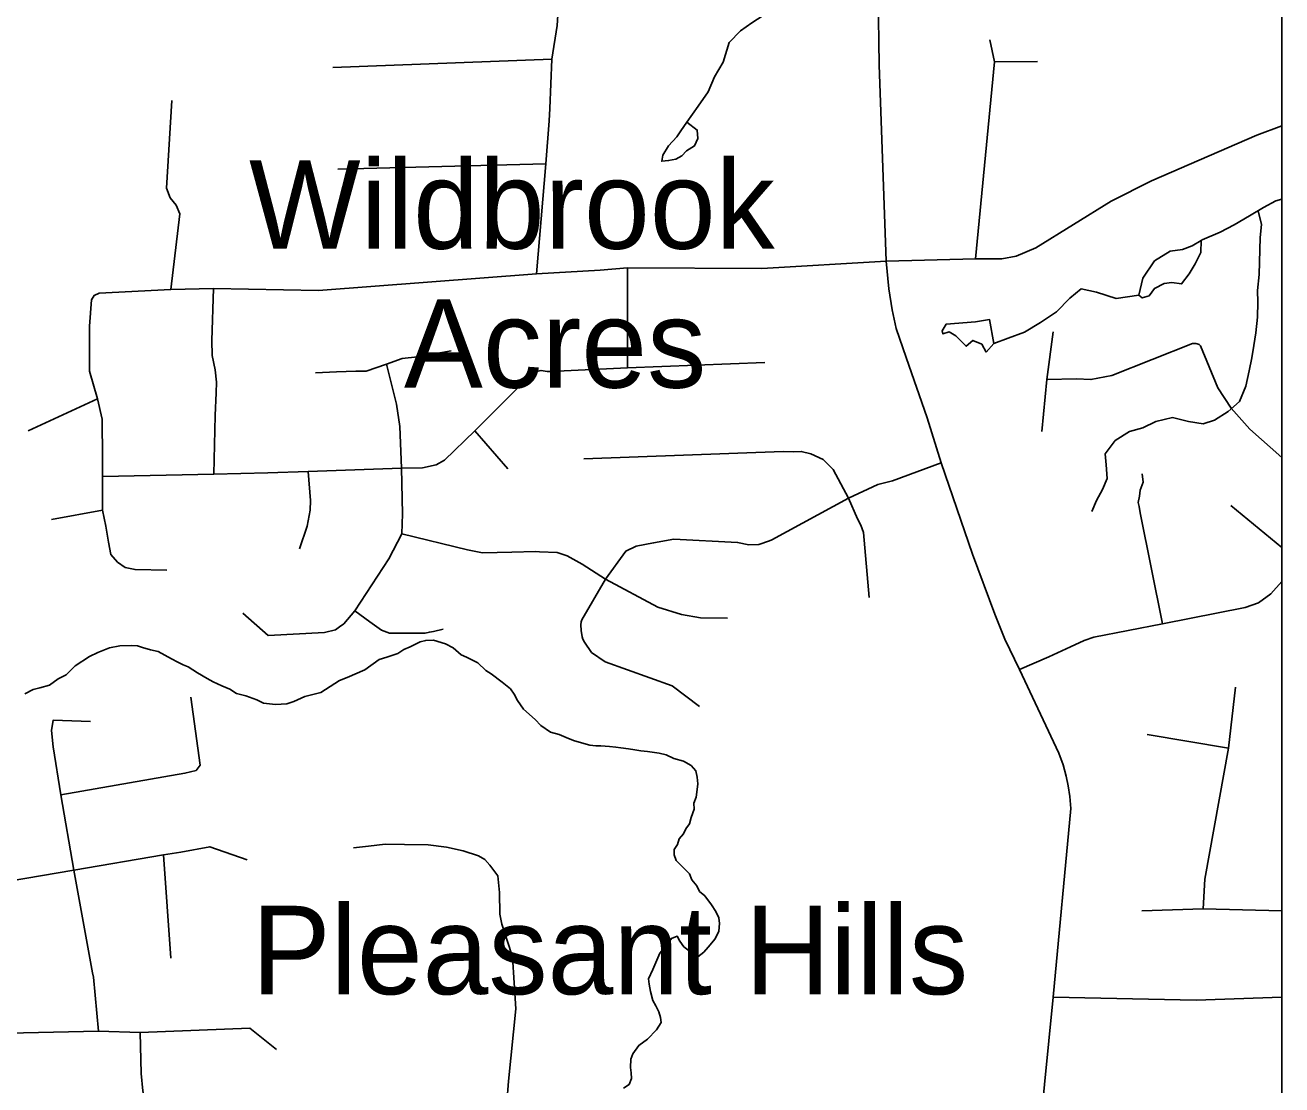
# Model space of a CAD drawing. Extents: x 0 to 34, y 0 to 22.
# Drawn here: x 7.678 to 8.8, y 16.382 to 17.329 of the extents above; entities that cross this region are included whole.
import ezdxf

# ---------------------------------------------------------------- set-up
doc = ezdxf.new("R2010")
doc.units = 0
for name, color, linetype in [('GM_X_County_Road', 7, 'Continuous'), ('GM_X_Minor_Lake', 7, 'Continuous'), ('GM_X_Minor_River', 7, 'Continuous'), ('GM_X_Township_Subdivision', 7, 'Continuous'), ('GM_X_Unincorporated_Text', 7, 'Continuous'), ('SH_Data', 7, 'Continuous')]:
    doc.layers.add(name, color=color, linetype=linetype)

msp = doc.modelspace()

# ---------------------------------------------------------------- linework, layer by layer
at = {"layer": 'GM_X_County_Road'}
for points in [[(8.5763, 16.2655), (8.5957, 16.4605), (8.6116, 16.6291), (8.6107, 16.6398), (8.609, 16.6494), (8.6074, 16.6579), (8.6047, 16.6681), (8.6008, 16.6786), (8.5656, 16.7531), (8.5526, 16.7802), (8.5437, 16.8026), (8.5238, 16.8562), (8.4957, 16.9379), (8.4832, 16.978), (8.4645, 17.0319), (8.4556, 17.0577), (8.4518, 17.0743), (8.4489, 17.0933), (8.4467, 17.1179), (8.4403, 17.2932), (8.4393, 17.3556)], [(8.4467, 17.1179), (8.5265, 17.1201), (8.5499, 17.1201), (8.5627, 17.1224), (8.5803, 17.1297), (8.6475, 17.1715), (8.6835, 17.1897), (8.7776, 17.2303), (8.8, 17.2387)], [(8.5957, 16.4605), (8.7235, 16.4578), (8.8, 16.4607)]]:
    msp.add_lwpolyline(points, dxfattribs=at)
at = {"layer": 'GM_X_Minor_Lake'}
for points in [[(8.2686, 17.2421), (8.2779, 17.2349), (8.2785, 17.2276), (8.2754, 17.2209), (8.2684, 17.2165), (8.2641, 17.212), (8.2588, 17.2091), (8.2523, 17.2077), (8.2462, 17.2071), (8.2471, 17.2127), (8.2522, 17.221), (8.2596, 17.2288), (8.2631, 17.2344)], [(8.2631, 17.2344), (8.2686, 17.2421)], [(8.728, 17.1364), (8.7275, 17.1257), (8.7227, 17.1156), (8.7172, 17.1066), (8.7105, 17.0976), (8.7018, 17.0989), (8.6949, 17.098), (8.6861, 17.0936), (8.6814, 17.0869), (8.6753, 17.0851), (8.6723, 17.0874), (8.6757, 17.1026), (8.6863, 17.1183), (8.7001, 17.1267), (8.7112, 17.1284), (8.72, 17.1316)], [(8.72, 17.1316), (8.728, 17.1364)], [(8.5426, 17.0444), (8.5389, 17.0657), (8.5263, 17.0637), (8.5001, 17.0616), (8.4965, 17.0556), (8.4972, 17.053), (8.5029, 17.0547), (8.5089, 17.0512), (8.5179, 17.0419), (8.524, 17.0471), (8.532, 17.0438), (8.536, 17.0365)], [(8.536, 17.0365), (8.5426, 17.0444)]]:
    msp.add_lwpolyline(points, dxfattribs=at)
at = {"layer": 'GM_X_Minor_River'}
for points in [[(8.4293, 17.4155), (8.4269, 17.4052), (8.4224, 17.3954), (8.4116, 17.3858), (8.4016, 17.3815), (8.3878, 17.3765), (8.3766, 17.3688), (8.3622, 17.3577), (8.351, 17.3474), (8.3367, 17.3374), (8.3266, 17.3308), (8.3166, 17.3235), (8.3064, 17.3131), (8.3011, 17.2957), (8.2932, 17.2826), (8.2875, 17.269), (8.2788, 17.2563), (8.2686, 17.2421)], [(8.7787, 17.1628), (8.7817, 17.1505), (8.7806, 17.1391), (8.7798, 17.106), (8.7783, 17.0916), (8.7785, 17.0813), (8.7781, 17.068), (8.7767, 17.054), (8.7749, 17.0426), (8.7731, 17.0317), (8.7709, 17.0199), (8.7679, 17.0063), (8.7622, 16.9927), (8.7521, 16.9835), (8.7398, 16.9758), (8.7298, 16.9726), (8.7166, 16.9748), (8.7022, 16.9782), (8.6873, 16.9748), (8.6758, 16.969), (8.6639, 16.9659), (8.6512, 16.9578), (8.6422, 16.9459), (8.6431, 16.9359), (8.6439, 16.9237), (8.6399, 16.914), (8.6343, 16.9042), (8.6303, 16.8944)], [(8.8, 17.1733), (8.7947, 17.1718), (8.7836, 17.1657), (8.7712, 17.1583), (8.7573, 17.1503), (8.745, 17.1438), (8.7289, 17.1369), (8.728, 17.1364)], [(8.6723, 17.0874), (8.6521, 17.0845), (8.6344, 17.0902), (8.6208, 17.0931), (8.6107, 17.085), (8.5987, 17.0727), (8.5844, 17.0632), (8.5702, 17.0544), (8.5556, 17.049), (8.5426, 17.0444)], [(7.6774, 16.7314), (7.6847, 16.7354), (7.6908, 16.7367), (7.6992, 16.7391), (7.707, 16.745), (7.7143, 16.7486), (7.7221, 16.7564), (7.7349, 16.7648), (7.7426, 16.7684), (7.7484, 16.7709), (7.753, 16.7727), (7.7622, 16.7743), (7.7728, 16.7748), (7.7778, 16.7743), (7.7823, 16.773), (7.7895, 16.7709), (7.7963, 16.7692), (7.8083, 16.7628), (7.8139, 16.7599), (7.8188, 16.7575), (7.8233, 16.7555), (7.8315, 16.7503), (7.8401, 16.7451), (7.8454, 16.7423), (7.8532, 16.7386), (7.8604, 16.7358), (7.8664, 16.7318), (7.8747, 16.7297), (7.8845, 16.726), (7.8905, 16.7231), (7.9011, 16.7221), (7.9114, 16.7226), (7.9175, 16.7247), (7.9275, 16.729), (7.9417, 16.7327), (7.9583, 16.7433), (7.9653, 16.7462), (7.981, 16.753), (7.9938, 16.7621), (8.0007, 16.7642), (8.0103, 16.7674), (8.0157, 16.771), (8.0215, 16.7735), (8.0304, 16.7779), (8.0354, 16.7792), (8.0422, 16.7794), (8.0531, 16.7761), (8.0599, 16.7725), (8.0669, 16.7662), (8.0718, 16.7641), (8.082, 16.7593), (8.089, 16.7522), (8.0939, 16.7494), (8.1036, 16.7419), (8.111, 16.736), (8.1143, 16.7313), (8.1172, 16.7256), (8.1227, 16.7178), (8.1331, 16.7087), (8.1383, 16.7033), (8.1468, 16.6973), (8.1544, 16.6952), (8.163, 16.6915), (8.1683, 16.6895), (8.1819, 16.6857), (8.1872, 16.6851), (8.1918, 16.685), (8.1994, 16.6844), (8.205, 16.6839), (8.2096, 16.6834), (8.2164, 16.6824), (8.2221, 16.6815), (8.2274, 16.6806), (8.2335, 16.68), (8.2437, 16.6786), (8.2501, 16.6769), (8.2569, 16.6737), (8.2656, 16.6715), (8.2723, 16.6675), (8.2767, 16.6628), (8.2777, 16.6571), (8.2783, 16.651), (8.2778, 16.646), (8.2768, 16.6392), (8.2748, 16.6339), (8.275, 16.6286), (8.2725, 16.6211), (8.2709, 16.6154), (8.2677, 16.6109), (8.2657, 16.6064), (8.2618, 16.6019), (8.2601, 16.597)], [(8.2601, 16.597), (8.2573, 16.5925), (8.2572, 16.5876), (8.259, 16.5826), (8.2664, 16.5752), (8.2708, 16.5708), (8.2729, 16.5654), (8.2774, 16.56), (8.2799, 16.555), (8.2847, 16.551), (8.2906, 16.5429), (8.2946, 16.537), (8.2971, 16.5313), (8.2977, 16.5263), (8.2972, 16.5195), (8.2939, 16.5127), (8.2877, 16.5052), (8.2837, 16.5008), (8.2783, 16.4967), (8.2731, 16.5003), (8.266, 16.5055), (8.2623, 16.5105), (8.2598, 16.5152), (8.2548, 16.513), (8.25, 16.5063), (8.2445, 16.5), (8.2381, 16.4853), (8.2344, 16.477), (8.235, 16.4721), (8.236, 16.4656), (8.2381, 16.4575), (8.241, 16.4529), (8.2435, 16.4475), (8.2449, 16.4425), (8.2455, 16.4379), (8.2415, 16.4315), (8.2333, 16.423), (8.2256, 16.4175), (8.2204, 16.41), (8.2184, 16.4051), (8.2182, 16.3979), (8.2188, 16.3929), (8.2191, 16.388), (8.217, 16.3827), (8.212, 16.3794)]]:
    msp.add_lwpolyline(points, dxfattribs=at)
at = {"layer": 'GM_X_Township_Subdivision'}
for points in [[(8.1461, 17.2541), (8.148, 17.2982), (8.1528, 17.3285), (8.1537, 17.3424)], [(8.5265, 17.1201), (8.5434, 17.2959), (8.5393, 17.3155)], [(7.9524, 17.2908), (8.148, 17.2982)], [(8.5434, 17.2959), (8.5816, 17.2961)], [(7.8077, 17.0927), (7.8158, 17.1603), (7.8125, 17.1679), (7.8072, 17.1745), (7.8039, 17.1832), (7.8085, 17.2614)], [(8.1343, 17.1065), (8.1425, 17.2049), (8.1457, 17.2433), (8.1461, 17.2541)], [(7.9567, 17.2002), (8.1425, 17.2049)], [(8.4467, 17.1179), (8.3354, 17.1114), (8.2156, 17.1119), (8.1912, 17.1098), (8.1343, 17.1065), (7.9395, 17.0917), (7.8457, 17.0934), (7.8077, 17.0927), (7.7436, 17.0894), (7.7391, 17.0873), (7.7369, 17.0833)], [(8.2156, 17.0225), (8.2156, 17.1119)], [(7.8457, 17.0934), (7.8442, 17.047), (7.8446, 17.0337), (7.8473, 17.0209), (7.8485, 17.0097), (7.8481, 17.0003), (7.8473, 16.9802), (7.8462, 16.9276)], [(7.7369, 17.0833), (7.7351, 17.0599), (7.7351, 17.0198), (7.7423, 16.9949), (7.7465, 16.9769), (7.7468, 16.9419), (7.7467, 16.9257), (7.7468, 16.8955), (7.7495, 16.8812), (7.7521, 16.8669), (7.7542, 16.856), (7.7602, 16.8491), (7.767, 16.8444), (7.7757, 16.8424), (7.8041, 16.8418)], [(8.5857, 16.9657), (8.5901, 17.0123), (8.5958, 17.0549)], [(8.5901, 17.0123), (8.6166, 17.0127), (8.6295, 17.0122), (8.6481, 17.0158), (8.7201, 17.0443), (8.7222, 17.0445), (8.7233, 17.0444), (8.7243, 17.0442), (8.7261, 17.0435), (8.7268, 17.043), (8.7273, 17.0423), (8.7429, 17.0049), (8.7548, 16.9865), (8.7713, 16.9678), (8.8, 16.9427)], [(7.9368, 17.0182), (7.9556, 17.019), (7.973, 17.0197), (7.9821, 17.0198), (8.0003, 17.0258), (8.0143, 17.031), (8.028, 17.0326), (8.0581, 17.0377)], [(7.7467, 16.9257), (7.8462, 16.9276), (7.8944, 16.9289), (7.9304, 16.9301), (8.0137, 16.933), (8.0324, 16.9334), (8.0446, 16.936), (8.0521, 16.9403), (8.0791, 16.9665), (8.1229, 17.01), (8.1299, 17.0167), (8.1342, 17.0194), (8.1384, 17.0204), (8.1437, 17.0194), (8.1464, 17.0195)], [(7.9583, 16.7912), (7.9622, 16.7941), (7.9721, 16.8056), (8.0024, 16.8521), (8.0139, 16.8743), (8.0146, 16.8921), (8.0137, 16.933), (8.0121, 16.9702), (8.0093, 16.9903), (8.0003, 17.0258)], [(8.1464, 17.0195), (8.2156, 17.0225), (8.3381, 17.0273)], [(7.6802, 16.9665), (7.7423, 16.9949)], [(8.0791, 16.9665), (8.1086, 16.9323)], [(8.1766, 16.9415), (8.3545, 16.9478), (8.3638, 16.9475), (8.3707, 16.948), (8.3792, 16.9459), (8.3903, 16.9409), (8.3991, 16.9319), (8.4128, 16.9061), (8.4211, 16.8879), (8.4241, 16.8822), (8.4263, 16.8757), (8.4314, 16.8176)], [(8.3444, 16.8691), (8.4128, 16.9061), (8.4392, 16.9184), (8.4522, 16.9218), (8.4957, 16.9379)], [(7.9227, 16.861), (7.9294, 16.8811), (7.9322, 16.8955), (7.9323, 16.9042), (7.9304, 16.9301)], [(8.6935, 16.7941), (8.6734, 16.8932), (8.6726, 16.8987), (8.6717, 16.9023), (8.6728, 16.9079), (8.6735, 16.9135), (8.6762, 16.9204), (8.6753, 16.9281)], [(7.701, 16.8873), (7.7468, 16.8955)], [(8.8, 16.8622), (8.7543, 16.8996)], [(8.0139, 16.8743), (8.0728, 16.86), (8.0862, 16.8575), (8.1123, 16.8579), (8.1334, 16.8585), (8.1371, 16.8584)], [(8.1371, 16.8584), (8.1526, 16.8578), (8.1616, 16.8546), (8.175, 16.8473), (8.1959, 16.8338), (8.214, 16.859), (8.2232, 16.8635), (8.2388, 16.8663), (8.2569, 16.8696), (8.3139, 16.8667), (8.324, 16.8645), (8.3328, 16.8648), (8.3423, 16.868), (8.3444, 16.8691)], [(8.1959, 16.8338), (8.1747, 16.7975), (8.1743, 16.7957), (8.174, 16.7932), (8.1742, 16.788), (8.1751, 16.7825), (8.1757, 16.7802), (8.1771, 16.7777), (8.1835, 16.7683), (8.1957, 16.76), (8.2556, 16.7386), (8.28, 16.7203)], [(8.1959, 16.8338), (8.2427, 16.809), (8.2639, 16.8023), (8.2809, 16.7994), (8.3048, 16.7992)], [(8.8, 16.8319), (8.7902, 16.8207), (8.779, 16.8127), (8.7672, 16.8085), (8.6935, 16.7941), (8.6321, 16.782), (8.6233, 16.779), (8.6111, 16.7735), (8.5919, 16.7644), (8.5656, 16.7531)], [(7.872, 16.8034), (7.8946, 16.7836), (7.9449, 16.7863), (7.9547, 16.7886), (7.9583, 16.7912)], [(7.9721, 16.8056), (7.9853, 16.7957), (7.9958, 16.7882), (8.0029, 16.7858), (8.0348, 16.7858), (8.0386, 16.7866), (8.0424, 16.7872), (8.0509, 16.7891)], [(8.7296, 16.5395), (8.7311, 16.5659), (8.7522, 16.683), (8.7585, 16.7373)], [(7.7093, 16.6414), (7.8203, 16.6605), (7.8303, 16.6631), (7.8338, 16.6678), (7.8255, 16.7285)], [(7.736, 16.7069), (7.7027, 16.708), (7.701, 16.6986), (7.7027, 16.6841), (7.7093, 16.6414), (7.7211, 16.5741), (7.7377, 16.4823)], [(8.7522, 16.683), (8.6797, 16.6953)], [(7.5407, 16.5266), (7.5754, 16.5245), (7.5942, 16.528), (7.6077, 16.5318), (7.6233, 16.5419), (7.6361, 16.5523), (7.6434, 16.5568), (7.6632, 16.5641), (7.7211, 16.5741), (7.8012, 16.5876), (7.8165, 16.5901), (7.8425, 16.5949), (7.8758, 16.5831)], [(7.9708, 16.5941), (7.9843, 16.5954), (7.999, 16.5971), (8.0164, 16.597), (8.0376, 16.5967), (8.0539, 16.5945), (8.0687, 16.5912), (8.0826, 16.5869), (8.0881, 16.5834), (8.0927, 16.5785)], [(7.8077, 16.4953), (7.8012, 16.5876)], [(8.1273, 16.3271), (8.1195, 16.3443), (8.1136, 16.354), (8.1078, 16.3666), (8.1092, 16.3855), (8.1158, 16.4501), (8.1129, 16.4965), (8.1033, 16.5259), (8.1016, 16.5346), (8.1013, 16.5541), (8.0996, 16.569), (8.0927, 16.5785)], [(8.675, 16.5377), (8.7296, 16.5395), (8.8, 16.5376)], [(7.7377, 16.4823), (7.7385, 16.4784), (7.743, 16.4302)], [(7.5312, 16.4263), (7.5571, 16.4253), (7.6223, 16.4274), (7.743, 16.4302), (7.7804, 16.4291), (7.8782, 16.4329), (7.9022, 16.4139)], [(7.7804, 16.4291), (7.7813, 16.3924), (7.7827, 16.3769), (7.7884, 16.3511), (7.7985, 16.2967), (7.8031, 16.2916), (7.8086, 16.2887), (7.8152, 16.2864), (7.8322, 16.2841), (7.8486, 16.2832)]]:
    msp.add_lwpolyline(points, dxfattribs=at)
at = {"layer": 'SH_Data'}
msp.add_line((8.8, 21), (8.8, 14.2), dxfattribs=at)

# ---------------------------------------------------------------- texts
at = {"layer": 'GM_X_Unincorporated_Text'}
for s, height, p in [('Wildbrook', 0.07898, (7.8775, 17.129)), ('Acres', 0.07898, (8.0159, 17.0049)), ('Pleasant Hills', 0.078977, (7.88, 16.4632))]:
    msp.add_text(s, height=height, rotation=0, dxfattribs=at).set_placement(p)

doc.saveas('drawing.dxf')
